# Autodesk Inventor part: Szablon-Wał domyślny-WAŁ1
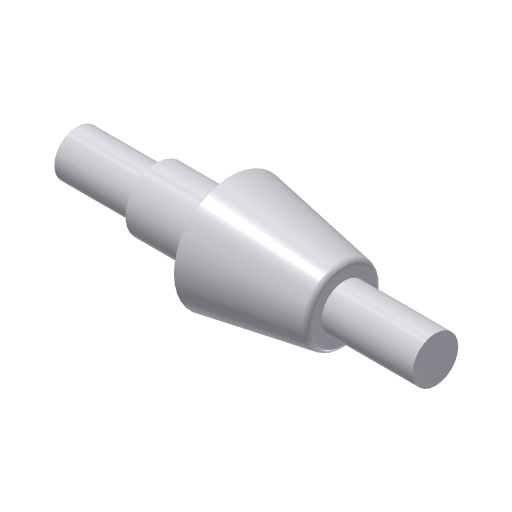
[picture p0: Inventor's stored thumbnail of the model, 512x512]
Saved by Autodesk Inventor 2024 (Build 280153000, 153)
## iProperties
Company: ATC
CustomPartVersion: 1
Created: 2023-03
Part Number: Szablon-Wał domyślny-WAŁ1
Material: Stal
Document SubType Name: Modeling
Designer: Andrzej Jaskulski
Density: 7.85 g/cm^3
Appearance: Kurs-AJ
Checked By: A.J.
Engr Approved By: Andrzej Jaskulski
Mfg Approved By: Andrzej Jaskulski
Authority: A.J.
Author: Andrzej Jaskulski
Title: A.J.: Kurs R2024-MEP
Revision Number: 1/24
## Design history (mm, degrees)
sketch "Szkic główny"
  geometry: L1 (0, 0)-(315, 0) reference; L2 (0, 0)-(0, 20); L3 (0, 20)-(70, 20); L4 (70, 20)-(70, 27.5); L5 (70, 27.5)-(135, 27.5); L6 (135, 27.5)-(135, 50); L7 (235, 32.5)-(235, 20); L8 (135, 50)-(235, 32.5); L9 (315, 20)-(315, 0); L10 (235, 20)-(315, 20)
  constraints: 20 end point, 5 horizontal, 5 vertical
  dimensions: "d3" = 40 diameter of L3 L1 (derived); "d4" = 55 diameter of L5 L1 (derived); "d5" = 40 diameter of L10 L1 (derived)
revolve "Obrót1" sketch "Szkic główny" stored, may be unused: angle "d6" = 0 deg
chamfer "Faza1" distance "d7" = 0.5; stored, may be unused: second distance "d8" = 0.125, angle "d9" = 45 deg
fillet "Zaokrąglenie1" dims "d10" = 5
chamfer "Faza2" distance "d11" = 0.5; stored, may be unused: second distance "d12" = 0.125, angle "d13" = 45 deg
chamfer "Faza3" distance "d14" = 0.5; stored, may be unused: second distance "d15" = 0.125, angle "d16" = 45 deg
fillet "Zaokrąglenie2" dims "d17" = 5
node "Bryła1"
other parameters: "d0" = 0, "d1" = 0, "d2" = 0
